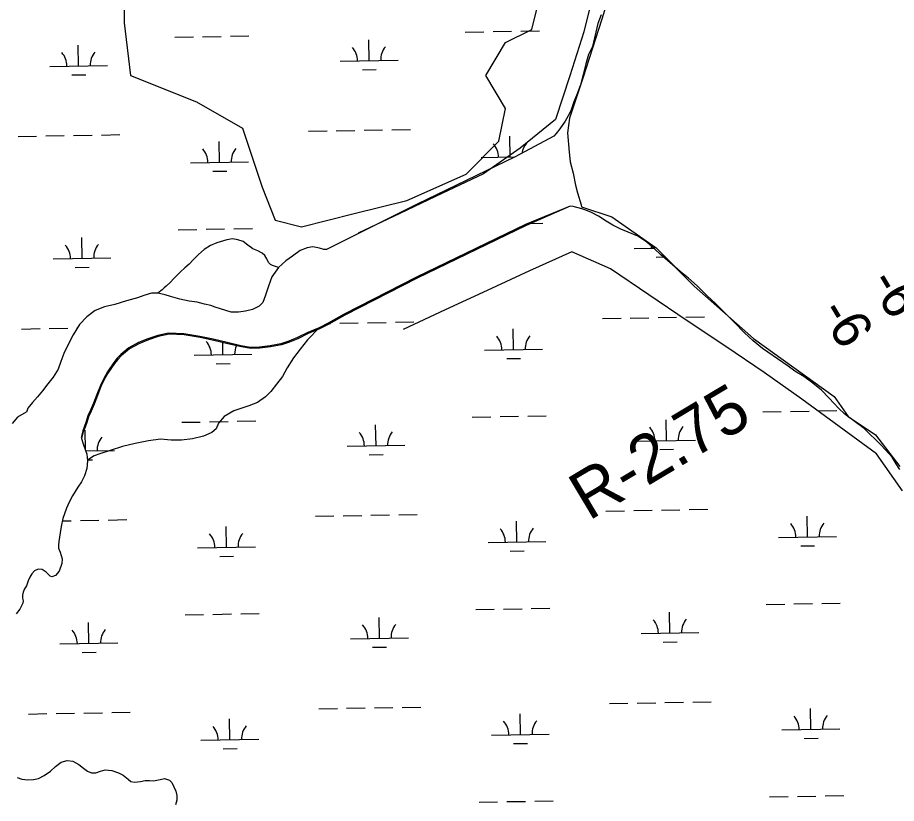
# Model space of a CAD drawing. Extents: x 3914892 to 3953151, y 242587 to 268572.
# Drawn here: x 3935694 to 3937212, y 254924 to 256282 of the extents above; entities that cross this region are included whole.
import ezdxf

# ---------------------------------------------------------------- set-up
doc = ezdxf.new("R2010")
doc.units = 0
for name, color, linetype in [('V-RIVR-EDGE', 7, 'Continuous'), ('V-RIVR-RANG', 7, 'Continuous'), ('V-RIVR-RANG-IDEN', 7, 'Continuous'), ('V-RRAP-FSHR', 7, 'Continuous'), ('V-SITE-VEGE', 7, 'Continuous'), ('V-TOPO-SHOR', 7, 'Continuous'), ('V-WETL-SWMP', 7, 'Continuous')]:
    doc.layers.add(name, color=color, linetype=linetype)

msp = doc.modelspace()

# ---------------------------------------------------------------- linework, layer by layer
at = {"layer": 'V-RIVR-EDGE'}
for points in [[(3935267.1, 258917.5), (3935281.5, 258909.6), (3935430, 258775.5), (3935519, 258690.6), (3935544.6, 258651.7), (3935683.8, 258351.7), (3935756.5, 258214.5), (3935945.9, 257868.5), (3936125.1, 257548.1), (3936199.8, 257424.2), (3936367.7, 257125.3), (3936456.7, 256983), (3936523.3, 256882.7), (3936577.5, 256790.6), (3936615.4, 256720.9), (3936660.5, 256649.3), (3936694.2, 256558.2), (3936699.4, 256532.6), (3936713.7, 256443.5), (3936723.9, 256389.3), (3936722.9, 256344.2), (3936703.5, 256279.7), (3936670.7, 256177.4), (3936647.6, 256108.2)], [(3936647.6, 256108.2), (3936644.1, 256082.8), (3936647.1, 256049.6), (3936648.9, 256033), (3936654.3, 256013.1), (3936658, 255992.6), (3936661.3, 255979.3), (3936667.9, 255958.5), (3936668.7, 255955.2)], [(3936668.6, 255955.2), (3936720.9, 255937.8), (3936797.6, 255884.6), (3936863.2, 255818), (3936965.5, 255727.9), (3937104.7, 255627.6), (3937129.3, 255592.8), (3937176.4, 255561.1), (3937218.4, 255506.8)]]:
    msp.add_lwpolyline(points, dxfattribs=at)
at = {"layer": 'V-RRAP-FSHR'}
for points in [[(3936691.3, 256335.5), (3936672.4, 256257.8), (3936648.6, 256181.4), (3936623.3, 256106.1), (3936562.5, 256056.4), (3936499.4, 256012.4), (3936427.1, 255978.2), (3936354.8, 255943.9), (3936282.5, 255909.7)], [(3937222.7, 255464.5), (3937178.3, 255528.4), (3937113.8, 255575.6), (3937049.2, 255622.8), (3936983.8, 255668.9), (3936917.5, 255713.7), (3936851.2, 255758.4), (3936784.9, 255803.2), (3936718.6, 255848), (3936651.6, 255877.5), (3936578.4, 255844.4), (3936505.8, 255810.5), (3936433.1, 255777.3), (3936360.5, 255743.5)]]:
    msp.add_lwpolyline(points, dxfattribs=at)
at = {"layer": 'V-SITE-VEGE'}
msp.add_lwpolyline([(3935878.2, 256329.8), (3935878.2, 256273), (3935889.5, 256182.1), (3936003.2, 256136.6), (3936082.7, 256091.2), (3936116.8, 255988.9), (3936139.5, 255932.1), (3936185, 255920.8), (3936275.9, 255943.5), (3936366.8, 255966.2), (3936469, 256011.7), (3936525.9, 256068.5), (3936537.2, 256125.3), (3936503.1, 256182.1), (3936537.2, 256238.9), (3936582.7, 256261.6), (3936605.4, 256352.5)], dxfattribs=at)
at = {"layer": 'V-TOPO-SHOR'}
for points in [[(3936620.7, 256077.4), (3936553.7, 256041.7), (3936384.8, 255959.9), (3936228.2, 255881.5), (3936223.6, 255881.3), (3936215.8, 255883.5), (3936204.4, 255886.2), (3936194.6, 255884.6), (3936182.4, 255879.5), (3936169.1, 255870.2), (3936157.7, 255861.9), (3936145, 255850.5), (3936133.4, 255834.2), (3936127.8, 255818.2), (3936122.8, 255802.8), (3936118.2, 255790), (3936111.8, 255783.5), (3936100.4, 255777.6), (3936088, 255774.7), (3936076.2, 255773.1), (3936063.5, 255773.3), (3936045.1, 255778.8), (3936035.7, 255781.9), (3936028, 255784.5), (3936017.2, 255787.3), (3936004.4, 255790.3), (3935990.7, 255792.4), (3935974.4, 255795.7), (3935958.7, 255800.2), (3935949.4, 255803.3), (3935936.8, 255806.2), (3935925.6, 255806.1), (3935912.7, 255802), (3935901.3, 255797.9), (3935882.3, 255792.9), (3935862.1, 255786.6), (3935844.6, 255782.5), (3935828.3, 255776.1), (3935814.1, 255764.9), (3935801.6, 255751.7), (3935790.3, 255734.1), (3935781.2, 255715.9), (3935774.4, 255701.9), (3935769.1, 255688.2), (3935764.4, 255674.6), (3935755.9, 255660.9), (3935746.6, 255649.4), (3935737.5, 255637.4), (3935728.8, 255627), (3935720.4, 255617), (3935712.3, 255607.5), (3935709.6, 255600.6)], [(3936649.1, 255956.3), (3936571.6, 255924.6), (3936383.5, 255833.5), (3936258.6, 255769.6), (3936231, 255754.4), (3936215.1, 255746.4), (3936195.5, 255738), (3936177.7, 255729.3), (3936163, 255723.2), (3936149.2, 255718.5), (3936130.4, 255715), (3936112.1, 255712.7), (3936096.9, 255712.4), (3936080.1, 255715.2), (3936056.4, 255720.5), (3936032.3, 255726.3), (3936009, 255731.2), (3935981.5, 255735.9), (3935955.3, 255737.1), (3935936.4, 255732.7), (3935919.6, 255727.1), (3935903.1, 255720.5), (3935886.8, 255711.5), (3935873, 255700), (3935866.6, 255693.5), (3935860.6, 255686.2), (3935849.5, 255669.9), (3935842.7, 255657.7), (3935837.4, 255646.6), (3935831.3, 255631), (3935825.6, 255615.9), (3935820.3, 255604), (3935815.9, 255594.1), (3935813.1, 255584.3), (3935810.2, 255576.1), (3935807, 255568.4), (3935804, 255556.7)], [(3936145, 255850.5), (3936134.9, 255853.6), (3936131, 255855.4), (3936127.8, 255858.9), (3936124.7, 255865.1), (3936121.4, 255871.1), (3936116.9, 255875.1), (3936109.2, 255879.1), (3936101, 255882.9), (3936091.9, 255888.9), (3936083.8, 255895.2), (3936075, 255898.4), (3936065.8, 255900), (3936055.8, 255898.1), (3936038.7, 255893.2), (3936027.6, 255888.3), (3936016.8, 255881.4), (3936006.7, 255872.7), (3935997.5, 255863.9), (3935990.7, 255856.4), (3935983.2, 255849.6), (3935975.6, 255842.9), (3935970.1, 255837.4), (3935964.8, 255832.1), (3935957.8, 255824.7), (3935951, 255817.9), (3935947.7, 255815.1), (3935944.4, 255812), (3935936.8, 255806.2)], [(3936215.1, 255746.4), (3936195.4, 255725.2), (3936182.7, 255709.2), (3936171, 255694.3), (3936160.2, 255677.2), (3936151.7, 255662.1), (3936141.5, 255648.9), (3936131.6, 255636.2), (3936122.4, 255626.7), (3936108.8, 255617.3), (3936093.8, 255611.2), (3936081.8, 255607.2), (3936067.7, 255602.9), (3936051.1, 255593), (3936041.2, 255581.2), (3936037.5, 255571.8), (3936029.7, 255565.1), (3936015.7, 255559.2), (3935996.5, 255554.2), (3935977.3, 255551.9), (3935959.9, 255552.1), (3935941.5, 255553.8), (3935920.4, 255551), (3935897.7, 255546.1), (3935875.6, 255541.3), (3935854.3, 255534.3), (3935836.5, 255528.3), (3935826.5, 255524.7), (3935815.3, 255517.5)]]:
    msp.add_lwpolyline(points, dxfattribs=at)
at = {"layer": 'V-WETL-SWMP'}
for p, q in [((3936467.8, 256257.1), (3936499.8, 256257.7)), ((3936515.8, 256258), (3936547.8, 256258.5)), ((3936563.8, 256258.8), (3936595.8, 256259.4)), ((3935966, 256248.1), (3935998, 256248.7)), ((3936014, 256249), (3936046, 256249.6)), ((3936062, 256249.8), (3936094, 256250.4)), ((3936301.6, 256207.7), (3936301, 256243.7)), ((3935799.8, 256198.7), (3935799.1, 256234.7)), ((3936251.6, 256206.8), (3936351.6, 256208.6)), ((3935749.8, 256197.8), (3935849.8, 256199.6)), ((3935788.1, 256183.1), (3935812.1, 256183.5)), ((3936289.9, 256192), (3936313.9, 256192.5)), ((3936244.9, 256086.6), (3936276.9, 256087.2)), ((3936292.9, 256087.4), (3936324.9, 256088)), ((3936340.9, 256088.3), (3936372.9, 256088.9)), ((3935695.1, 256076.7), (3935727.1, 256077.3)), ((3935743.1, 256077.6), (3935775.1, 256078.2)), ((3935791.1, 256078.5), (3935823.1, 256079)), ((3935839.1, 256079.3), (3935871.1, 256079.9)), ((3936196.9, 256085.7), (3936228.9, 256086.3)), ((3936545.1, 256041.2), (3936544.5, 256077.2)), ((3936043.3, 256032.2), (3936042.6, 256068.2)), ((3935993.3, 256031.3), (3936093.3, 256033.1)), ((3936495.1, 256040.3), (3936552.9, 256041.3)), ((3936031.6, 256016.6), (3936055.6, 256017)), ((3936649.1, 255956.3), (3936572.6, 255922.7)), ((3936653.8, 255955.9), (3936649.1, 255956.3)), ((3936668.8, 255952), (3936653.8, 255955.9)), ((3936676.1, 255949.3), (3936668.8, 255952)), ((3936685.5, 255945.6), (3936676.1, 255949.3)), ((3936697.9, 255939.1), (3936685.5, 255945.6)), ((3936711.2, 255930.7), (3936697.9, 255939.1)), ((3936572.6, 255922.7), (3936384.4, 255831.7)), ((3936580.9, 255926.4), (3936601.8, 255926.8)), ((3936722.8, 255923.5), (3936711.2, 255930.7)), ((3936736.5, 255916.4), (3936722.8, 255923.5)), ((3935971.9, 255915.5), (3936003.9, 255916.1)), ((3936019.9, 255916.4), (3936051.9, 255916.9)), ((3936067.9, 255917.2), (3936099.9, 255917.8)), ((3936748.9, 255911.2), (3936736.5, 255916.4)), ((3936765.6, 255904.6), (3936748.9, 255911.2)), ((3935805.7, 255866.1), (3935805.1, 255902.1)), ((3936781.1, 255894.3), (3936765.6, 255904.6)), ((3936794.7, 255882.6), (3936781.1, 255894.3)), ((3936759.4, 255883.1), (3936793.3, 255883.8)), ((3936805.6, 255872.3), (3936794.7, 255882.6)), ((3935755.7, 255865.2), (3935855.7, 255867)), ((3936797.7, 255868.4), (3936809.8, 255868.6)), ((3936820.8, 255859), (3936805.6, 255872.3)), ((3935794, 255850.4), (3935818, 255850.9)), ((3936838.7, 255843.7), (3936820.8, 255859)), ((3936384.4, 255831.7), (3936259.5, 255767.8)), ((3936853.1, 255832), (3936838.7, 255843.7)), ((3936868, 255818.7), (3936853.1, 255832)), ((3936884.9, 255802), (3936868, 255818.7)), ((3936900.4, 255787.4), (3936884.9, 255802)), ((3936914.2, 255773.5), (3936900.4, 255787.4)), ((3936932.7, 255755.2), (3936914.2, 255773.5)), ((3936259.5, 255767.8), (3936231.9, 255752.5)), ((3936234, 255753.7), (3936234.9, 255753.7)), ((3936250.9, 255754), (3936282.9, 255754.5)), ((3936298.9, 255754.8), (3936330.9, 255755.4)), ((3936346.9, 255755.7), (3936378.9, 255756.3)), ((3936704.7, 255762.1), (3936736.7, 255762.7)), ((3936752.7, 255762.9), (3936784.7, 255763.5)), ((3936800.7, 255763.8), (3936832.7, 255764.4)), ((3936848.7, 255764.7), (3936880.7, 255765.2)), ((3936949.9, 255737.7), (3936932.7, 255755.2)), ((3935701.1, 255744.1), (3935733.1, 255744.7)), ((3935749.1, 255745), (3935781, 255745.6)), ((3935797, 255745.8), (3935797.8, 255745.9)), ((3936216, 255744.6), (3936196.4, 255736.2)), ((3936231.9, 255752.5), (3936216, 255744.6)), ((3936551.1, 255708.6), (3936550.4, 255744.6)), ((3935920.5, 255725.2), (3935904.1, 255718.6)), ((3935937.4, 255730.9), (3935920.5, 255725.2)), ((3935956.2, 255735.3), (3935937.4, 255730.9)), ((3935982.4, 255734.1), (3935956.2, 255735.3)), ((3936009.9, 255729.4), (3935982.4, 255734.1)), ((3936033.2, 255724.4), (3936009.9, 255729.4)), ((3936057.4, 255718.6), (3936033.2, 255724.4)), ((3936178.6, 255727.4), (3936163.9, 255721.3)), ((3936196.4, 255736.2), (3936178.6, 255727.4)), ((3936964.8, 255723.5), (3936949.9, 255737.7)), ((3936981.2, 255710.6), (3936964.8, 255723.5)), ((3935887.7, 255709.6), (3935873.9, 255698.1)), ((3935904.1, 255718.6), (3935887.7, 255709.6)), ((3936049.2, 255699.6), (3936048.9, 255720.7)), ((3936081.1, 255713.4), (3936057.4, 255718.6)), ((3936097.8, 255710.6), (3936081.1, 255713.4)), ((3936113.1, 255710.8), (3936097.8, 255710.6)), ((3936131.3, 255713.1), (3936113.1, 255710.8)), ((3936150.1, 255716.6), (3936131.3, 255713.1)), ((3936163.9, 255721.3), (3936150.1, 255716.6)), ((3936501.1, 255707.7), (3936601, 255709.5)), ((3937025.2, 255679.7), (3936981.2, 255710.6)), ((3935873.9, 255698.1), (3935867.5, 255691.6)), ((3935999.2, 255698.7), (3936099.2, 255700.5)), ((3936539.3, 255692.9), (3936563.3, 255693.4)), ((3935861.6, 255684.4), (3935850.5, 255668)), ((3935867.5, 255691.6), (3935861.6, 255684.4)), ((3936037.5, 255684), (3936061.5, 255684.4)), ((3937036.7, 255671.4), (3937025.2, 255679.7)), ((3935850.5, 255668), (3935843.6, 255655.8)), ((3937052.8, 255661.8), (3937036.7, 255671.4)), ((3935843.6, 255655.8), (3935838.3, 255644.7)), ((3937068.2, 255650.7), (3937052.8, 255661.8)), ((3937083, 255638.3), (3937068.2, 255650.7)), ((3935838.3, 255644.7), (3935832.3, 255629.1)), ((3937095.5, 255625.3), (3937083, 255638.3)), ((3935832.3, 255629.1), (3935826.5, 255614)), ((3937104.8, 255615.6), (3937095.5, 255625.3)), ((3935821.2, 255602.2), (3935816.8, 255592.3)), ((3935826.5, 255614), (3935821.2, 255602.2)), ((3936981.6, 255600.8), (3937013.5, 255601.4)), ((3937029.5, 255601.7), (3937061.5, 255602.3)), ((3937077.5, 255602.6), (3937109.5, 255603.1)), ((3937112.4, 255607.2), (3937104.8, 255615.6)), ((3937123.3, 255597), (3937112.4, 255607.2)), ((3935816.8, 255592.3), (3935814, 255582.4)), ((3936479.7, 255591.9), (3936511.7, 255592.4)), ((3936527.7, 255592.7), (3936559.7, 255593.3)), ((3936575.7, 255593.6), (3936607.7, 255594.1)), ((3936815.3, 255551.4), (3936814.7, 255587.4)), ((3937156.8, 255572.1), (3937123.3, 255597)), ((3935811.1, 255574.3), (3935807.9, 255566.6)), ((3935814, 255582.4), (3935811.1, 255574.3)), ((3935977.9, 255582.9), (3936009.9, 255583.4)), ((3936025.9, 255583.7), (3936057.9, 255584.3)), ((3936073.9, 255584.6), (3936105.9, 255585.2)), ((3936313.5, 255542.4), (3936312.9, 255578.4)), ((3937186.2, 255543.3), (3937156.8, 255572.1)), ((3935807.9, 255566.6), (3935804.9, 255554.8)), ((3935811.7, 255535), (3935811, 255569.5)), ((3935804.9, 255554.8), (3935807.9, 255545.7)), ((3935807.9, 255545.7), (3935811.4, 255535.7)), ((3936263.5, 255541.5), (3936363.5, 255543.3)), ((3936765.4, 255550.5), (3936865.3, 255552.3)), ((3937205, 255522.5), (3937186.2, 255543.3)), ((3935811.4, 255535.7), (3935813.9, 255527.6)), ((3935812.1, 255533.5), (3935861.7, 255534.4)), ((3935813.9, 255527.6), (3935815.4, 255516.6)), ((3936301.8, 255526.8), (3936325.8, 255527.2)), ((3936803.6, 255535.8), (3936827.6, 255536.2)), ((3935815.4, 255516.6), (3935813.8, 255502.9)), ((3935815.2, 255518.1), (3935824, 255518.3)), ((3937212.2, 255511.1), (3937205, 255522.5)), ((3937218.4, 255501.5), (3937212.2, 255511.1)), ((3935813.8, 255502.9), (3935809.9, 255490.7)), ((3935804.6, 255480.1), (3935798.3, 255470.6)), ((3935809.9, 255490.7), (3935804.6, 255480.1)), ((3935798.3, 255470.6), (3935789.1, 255455.9)), ((3935789.1, 255455.9), (3935783.7, 255445)), ((3935783.7, 255445), (3935778.7, 255434.3)), ((3935778.7, 255434.3), (3935772.7, 255416.9)), ((3936208.8, 255420.5), (3936240.8, 255421.1)), ((3936256.8, 255421.3), (3936288.8, 255421.9)), ((3936304.8, 255422.2), (3936336.8, 255422.8)), ((3936352.8, 255423.1), (3936384.8, 255423.6)), ((3936710.7, 255429.5), (3936742.7, 255430)), ((3936758.7, 255430.3), (3936790.7, 255430.9)), ((3936806.7, 255431.2), (3936838.6, 255431.7)), ((3936854.6, 255432), (3936886.6, 255432.6)), ((3937058.8, 255384.9), (3937058.2, 255420.9)), ((3935772.7, 255416.9), (3935769.6, 255403.1)), ((3935771.8, 255412.7), (3935787, 255412.9)), ((3935803, 255413.2), (3935835, 255413.8)), ((3935851, 255414.1), (3935883, 255414.7)), ((3936557, 255376), (3936556.4, 255412)), ((3935767.9, 255391.9), (3935765.4, 255376.7)), ((3935769.6, 255403.1), (3935767.9, 255391.9)), ((3936055.2, 255367), (3936054.5, 255403)), ((3935765.4, 255376.7), (3935764.9, 255370.6)), ((3936507, 255375.1), (3936607, 255376.9)), ((3937008.8, 255384), (3937108.8, 255385.8)), ((3935764.9, 255370.6), (3935764.8, 255365.5)), ((3935764.8, 255365.5), (3935768.2, 255358.8)), ((3935768.2, 255358.8), (3935771.4, 255347.2)), ((3936005.2, 255366.1), (3936105.2, 255367.9)), ((3936545.3, 255360.3), (3936569.3, 255360.7)), ((3937047.1, 255369.3), (3937071.1, 255369.7)), ((3935771.4, 255347.2), (3935770.9, 255339.2)), ((3936043.5, 255351.3), (3936067.5, 255351.8)), ((3935730.2, 255329.3), (3935723.8, 255326.2)), ((3935737, 255328.7), (3935730.2, 255329.3)), ((3935744, 255323.7), (3935737, 255328.7)), ((3935770.9, 255339.2), (3935766.3, 255325.7)), ((3935715.7, 255315.3), (3935712.9, 255309.2)), ((3935719, 255320.9), (3935715.7, 255315.3)), ((3935723.8, 255326.2), (3935719, 255320.9)), ((3935750.6, 255316.9), (3935744, 255323.7)), ((3935753.8, 255315.7), (3935750.6, 255316.9)), ((3935759.8, 255318.3), (3935753.8, 255315.7)), ((3935766.3, 255325.7), (3935759.8, 255318.3)), ((3935709.8, 255300.5), (3935706.1, 255295.1)), ((3935712.9, 255309.2), (3935709.8, 255300.5)), ((3935703.8, 255289.3), (3935703.1, 255284.2)), ((3935703.1, 255284.2), (3935703.1, 255279.2)), ((3935706.1, 255295.1), (3935703.8, 255289.3)), ((3935703.7, 255270.2), (3935698, 255259.9)), ((3935703.1, 255279.2), (3935704, 255274.5)), ((3935704, 255274.5), (3935703.7, 255270.2)), ((3936987.5, 255268.2), (3937019.5, 255268.8)), ((3937035.5, 255269.1), (3937067.5, 255269.6)), ((3937083.5, 255269.9), (3937115.5, 255270.5)), ((3935698, 255259.9), (3935692.2, 255251.9)), ((3936079.8, 255252), (3936111.8, 255252.5)), ((3936485.7, 255259.2), (3936517.7, 255259.8)), ((3936533.7, 255260.1), (3936565.7, 255260.7)), ((3936581.7, 255261), (3936613.7, 255261.5)), ((3936821.3, 255218.8), (3936820.7, 255254.8)), ((3935983.8, 255250.3), (3936015.8, 255250.8)), ((3936031.8, 255251.1), (3936063.8, 255251.7)), ((3936319.5, 255209.8), (3936318.8, 255245.8)), ((3935817.6, 255200.8), (3935817, 255236.8)), ((3936269.5, 255208.9), (3936369.5, 255210.7)), ((3936771.3, 255217.9), (3936871.3, 255219.7)), ((3935767.6, 255199.9), (3935867.6, 255201.7)), ((3936307.7, 255194.2), (3936331.7, 255194.6)), ((3936809.6, 255203.2), (3936833.6, 255203.6)), ((3935805.9, 255185.2), (3935829.9, 255185.6)), ((3936214.8, 255087.9), (3936246.8, 255088.4)), ((3936262.8, 255088.7), (3936294.8, 255089.3)), ((3936310.8, 255089.6), (3936342.8, 255090.1)), ((3936358.8, 255090.4), (3936390.8, 255091)), ((3936716.6, 255096.8), (3936748.6, 255097.4)), ((3936764.6, 255097.7), (3936796.6, 255098.3)), ((3936812.6, 255098.6), (3936844.6, 255099.1)), ((3936860.6, 255099.4), (3936892.6, 255100)), ((3937064.8, 255052.3), (3937064.1, 255088.3)), ((3935713, 255078.9), (3935745, 255079.5)), ((3935761, 255079.7), (3935792.9, 255080.3)), ((3935808.9, 255080.6), (3935840.9, 255081.2)), ((3935856.9, 255081.5), (3935888.9, 255082)), ((3936061.1, 255034.4), (3936060.5, 255070.4)), ((3936563, 255043.3), (3936562.3, 255079.3)), ((3936513, 255042.4), (3936612.9, 255044.2)), ((3937014.8, 255051.4), (3937114.8, 255053.2)), ((3936011.1, 255033.5), (3936111.1, 255035.3)), ((3936551.2, 255027.7), (3936575.2, 255028.1)), ((3937053.1, 255036.7), (3937077.1, 255037.1)), ((3936049.4, 255018.7), (3936073.4, 255019.1)), ((3935759.7, 254988), (3935769.4, 254995.9)), ((3935769.4, 254995.9), (3935780.3, 254998.8)), ((3935780.3, 254998.8), (3935790, 254997.2)), ((3935790, 254997.2), (3935800.1, 254991.8)), ((3935740.1, 254972.4), (3935751.5, 254980.1)), ((3935751.5, 254980.1), (3935759.7, 254988)), ((3935800.1, 254991.8), (3935808.5, 254985.2)), ((3935808.5, 254985.2), (3935815.2, 254980.4)), ((3935815.2, 254980.4), (3935822.3, 254977.4)), ((3935829.8, 254977.1), (3935837.7, 254980.2)), ((3935837.7, 254980.2), (3935845.7, 254982.7)), ((3935845.7, 254982.7), (3935856.9, 254981.3)), ((3935856.9, 254981.3), (3935868.8, 254977.2)), ((3935693.6, 254969.3), (3935702, 254966.3)), ((3935702, 254966.3), (3935712.2, 254965.2)), ((3935712.2, 254965.2), (3935721.7, 254965.9)), ((3935721.7, 254965.9), (3935730.7, 254967.7)), ((3935730.7, 254967.7), (3935740.1, 254972.4)), ((3935822.3, 254977.4), (3935829.8, 254977.1)), ((3935868.8, 254977.2), (3935876.8, 254973.2)), ((3935876.8, 254973.2), (3935885.2, 254966.3)), ((3935885.2, 254966.3), (3935890.2, 254962.2)), ((3935906.9, 254962.2), (3935914.6, 254964.2)), ((3935914.6, 254964.2), (3935922.4, 254964.2)), ((3935922.4, 254964.2), (3935929.2, 254963.2)), ((3935929.2, 254963.2), (3935940.7, 254966)), ((3935940.7, 254966), (3935948.4, 254967.3)), ((3935948.4, 254967.3), (3935956.9, 254964.7)), ((3935956.9, 254964.7), (3935961.1, 254960.3)), ((3935890.2, 254962.2), (3935896.1, 254960.9)), ((3935896.1, 254960.9), (3935906.9, 254962.2)), ((3935961.1, 254960.3), (3935964.5, 254953.2)), ((3935964.5, 254953.2), (3935968, 254945.4)), ((3935968, 254945.4), (3935969.7, 254938)), ((3935969.7, 254938), (3935969.7, 254930.1)), ((3936993.5, 254935.6), (3937025.4, 254936.2)), ((3937041.4, 254936.4), (3937073.4, 254937)), ((3937089.4, 254937.3), (3937121.4, 254937.9)), ((3935969.7, 254930.1), (3935967.3, 254921.9)), ((3936491.6, 254926.6), (3936523.6, 254927.2)), ((3936539.6, 254927.5), (3936571.6, 254928)), ((3936587.6, 254928.3), (3936619.6, 254928.9))]:
    msp.add_line(p, q, dxfattribs=at)
for points in [[(3936702.6, 256286.7), (3936696.7, 256271.9), (3936687.3, 256232.5), (3936680.4, 256218.3), (3936675.7, 256202.1), (3936671.4, 256184), (3936666.7, 256165.8), (3936661.1, 256150.7), (3936655.2, 256136.5), (3936650.7, 256123), (3936647.8, 256116.2), (3936640.4, 256103.3), (3936631.1, 256089.8), (3936624.6, 256081.9), (3936620.7, 256077.4)], [(3936620.7, 256077.4), (3936553.7, 256041.7), (3936384.8, 255959.9), (3936228.2, 255881.5), (3936223.6, 255881.3), (3936215.8, 255883.5), (3936204.4, 255886.2), (3936194.6, 255884.6), (3936182.4, 255879.5), (3936169.1, 255870.2), (3936157.7, 255861.9), (3936145, 255850.5), (3936133.4, 255834.2), (3936127.8, 255818.2), (3936122.8, 255802.8), (3936118.2, 255790), (3936111.8, 255783.5), (3936100.4, 255777.6), (3936088, 255774.7), (3936076.2, 255773.1), (3936063.5, 255773.3), (3936045.1, 255778.8), (3936035.7, 255781.9), (3936028, 255784.5), (3936017.2, 255787.3), (3936004.4, 255790.3), (3935990.7, 255792.4), (3935974.4, 255795.7), (3935958.7, 255800.2), (3935949.4, 255803.3), (3935936.8, 255806.2), (3935925.6, 255806.1), (3935912.7, 255802), (3935901.3, 255797.9), (3935882.3, 255792.9), (3935862.1, 255786.6), (3935844.6, 255782.5), (3935828.3, 255776.1), (3935814.1, 255764.9), (3935801.6, 255751.7), (3935790.3, 255734.1), (3935781.2, 255715.9), (3935774.4, 255701.9), (3935769.1, 255688.2), (3935764.4, 255674.6), (3935755.9, 255660.9), (3935746.6, 255649.4), (3935737.5, 255637.4), (3935728.8, 255627), (3935720.4, 255617), (3935712.3, 255607.5), (3935709.6, 255600.6), (3935709.2, 255600.3), (3935694.4, 255591.6), (3935684.8, 255580.9)]]:
    msp.add_lwpolyline(points, dxfattribs=at)
for centre, start, end in [((3936246.4, 256207.2), 0.2532, 41.7968), ((3936356.8, 256209.2), 140.2532, 181.7968), ((3935744.5, 256198.2), 0.2532, 41.7968), ((3935855, 256200.2), 140.2532, 181.7968), ((3936489.9, 256040.7), 0.2532, 41.7968), ((3936600.3, 256042.7), 140.2532, 171.3135), ((3935988, 256031.7), 0.2532, 41.7968), ((3936098.5, 256033.7), 140.2532, 181.7968), ((3935861, 255867.6), 140.2532, 181.7968), ((3935750.5, 255865.6), 0.2532, 41.7968), ((3936754.2, 255883.5), 0.2532, 6.1967), ((3936495.8, 255708.1), 0.2532, 41.7968), ((3936606.3, 255710), 140.2532, 181.7968), ((3935994, 255699.1), 0.2532, 41.7968), ((3936104.5, 255701.1), 156.1153, 181.7968), ((3936760.1, 255550.9), 0.2532, 41.7968), ((3936870.6, 255552.9), 140.2532, 181.7968), ((3935866.9, 255534.9), 140.2532, 181.7968), ((3936258.3, 255541.9), 0.2532, 41.7968), ((3936368.7, 255543.9), 140.2532, 181.7968), ((3937003.6, 255384.4), 0.2532, 41.7968), ((3937114.1, 255386.4), 140.2532, 181.7968), ((3935999.9, 255366.5), 0.2532, 41.7968), ((3936110.4, 255368.4), 140.2532, 181.7968), ((3936501.8, 255375.4), 0.2532, 41.7968), ((3936612.2, 255377.4), 140.2532, 181.7968), ((3936766.1, 255218.3), 0.2532, 41.7968), ((3936876.5, 255220.3), 140.2532, 181.7968), ((3935762.4, 255200.3), 0.2532, 41.7968), ((3935872.9, 255202.3), 140.2532, 181.7968), ((3936264.2, 255209.3), 0.2532, 41.7968), ((3936374.7, 255211.3), 140.2532, 181.7968), ((3937009.5, 255051.8), 0.2532, 41.7968), ((3937120, 255053.8), 140.2532, 181.7968), ((3936005.9, 255033.8), 0.2532, 41.7968), ((3936116.4, 255035.8), 140.2532, 181.7968), ((3936507.7, 255042.8), 0.2532, 41.7968), ((3936618.2, 255044.8), 140.2532, 181.7968)]:
    msp.add_arc(centre, 35.2, start, end, dxfattribs=at)

# ---------------------------------------------------------------- texts
at = {"layer": 'V-RIVR-RANG'}
for p in [(3937163.5, 255825.2), (3937077.7, 255773.9)]:
    msp.add_text('-6', height=67, rotation=300.981, dxfattribs=at).set_placement(p)
at = {"layer": 'V-RIVR-RANG-IDEN'}
msp.add_text('R-2.75', height=83, rotation=30.8394, dxfattribs=at).set_placement((3936680.9, 255411.8))

doc.saveas('drawing.dxf')
